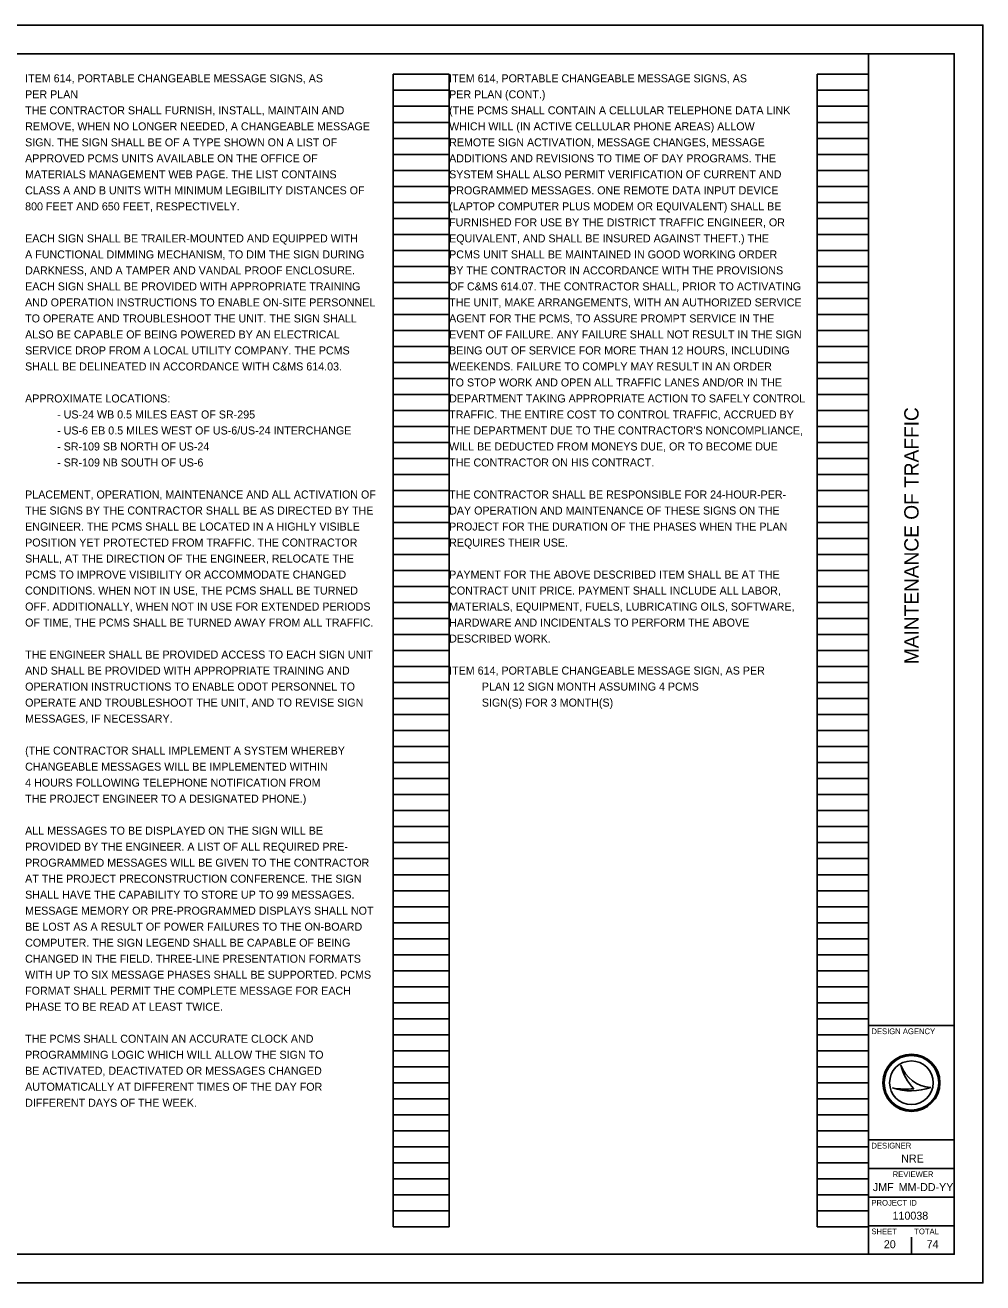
# Model space of a CAD drawing. Extents: x 0 to 34, y 0 to 22.
# Drawn here: x 17.24 to 34, y 0 to 22 of the extents above; entities that cross this region are included whole.
import ezdxf

# ---------------------------------------------------------------- set-up
doc = ezdxf.new("R2010")
doc.units = 0
for name, color, linetype in [('SH_Border', 7, 'Continuous'), ('SH_Cut_Line', 7, 'Continuous'), ('SH_Data', 7, 'Continuous'), ('SH_Text', 7, 'Continuous')]:
    doc.layers.add(name, color=color, linetype=linetype)

msp = doc.modelspace()

# ---------------------------------------------------------------- linework, layer by layer
at = {"layer": 'SH_Border'}
for p, q in [((32, 0.5), (32, 21.5)), ((32, 4.5), (33.5, 4.5)), ((32, 2.5), (33.5, 2.5)), ((32, 2), (33.5, 2)), ((32, 1.5), (33.5, 1.5)), ((32, 1), (33.5, 1))]:
    msp.add_line(p, q, dxfattribs=at)
msp.add_lwpolyline([(1.5, 21.5), (33.5, 21.5), (33.5, 0.5), (1.5, 0.5)], close=True, dxfattribs=at)
at = {"layer": 'SH_Cut_Line'}
msp.add_lwpolyline([(0, 0), (34, 0), (34, 22), (0, 22)], close=True, dxfattribs=at)
at = {"layer": 'SH_Data'}
for p, q in [((23.68, 0.98), (23.68, 21.14)), ((23.68, 21.14), (24.66, 21.14)), ((24.66, 0.98), (24.66, 21.14)), ((31.1, 0.98), (31.1, 21.14)), ((31.1, 21.14), (32, 21.14)), ((32, 0.98), (32, 21.14)), ((23.68, 20.86), (24.66, 20.86)), ((31.1, 20.86), (32, 20.86)), ((23.68, 20.58), (24.66, 20.58)), ((31.1, 20.58), (32, 20.58)), ((23.68, 20.3), (24.66, 20.3)), ((31.1, 20.3), (32, 20.3)), ((23.68, 20.02), (24.66, 20.02)), ((31.1, 20.02), (32, 20.02)), ((23.68, 19.74), (24.66, 19.74)), ((31.1, 19.74), (32, 19.74)), ((23.68, 19.46), (24.66, 19.46)), ((31.1, 19.46), (32, 19.46)), ((23.68, 19.18), (24.66, 19.18)), ((31.1, 19.18), (32, 19.18)), ((23.68, 18.9), (24.66, 18.9)), ((31.1, 18.9), (32, 18.9)), ((23.68, 18.62), (24.66, 18.62)), ((31.1, 18.62), (32, 18.62)), ((23.68, 18.34), (24.66, 18.34)), ((31.1, 18.34), (32, 18.34)), ((23.68, 18.06), (24.66, 18.06)), ((31.1, 18.06), (32, 18.06)), ((23.68, 17.78), (24.66, 17.78)), ((31.1, 17.78), (32, 17.78)), ((23.68, 17.5), (24.66, 17.5)), ((31.1, 17.5), (32, 17.5)), ((23.68, 17.22), (24.66, 17.22)), ((31.1, 17.22), (32, 17.22)), ((23.68, 16.94), (24.66, 16.94)), ((31.1, 16.94), (32, 16.94)), ((23.68, 16.66), (24.66, 16.66)), ((31.1, 16.66), (32, 16.66)), ((23.68, 16.38), (24.66, 16.38)), ((31.1, 16.38), (32, 16.38)), ((23.68, 16.1), (24.66, 16.1)), ((31.1, 16.1), (32, 16.1)), ((23.68, 15.82), (24.66, 15.82)), ((31.1, 15.82), (32, 15.82)), ((23.68, 15.54), (24.66, 15.54)), ((31.1, 15.54), (32, 15.54)), ((23.68, 15.26), (24.66, 15.26)), ((31.1, 15.26), (32, 15.26)), ((23.68, 14.98), (24.66, 14.98)), ((31.1, 14.98), (32, 14.98)), ((23.68, 14.7), (24.66, 14.7)), ((31.1, 14.7), (32, 14.7)), ((23.68, 14.42), (24.66, 14.42)), ((31.1, 14.42), (32, 14.42)), ((23.68, 14.14), (24.66, 14.14)), ((31.1, 14.14), (32, 14.14)), ((23.68, 13.86), (24.66, 13.86)), ((31.1, 13.86), (32, 13.86)), ((23.68, 13.58), (24.66, 13.58)), ((31.1, 13.58), (32, 13.58)), ((23.68, 13.3), (24.66, 13.3)), ((31.1, 13.3), (32, 13.3)), ((23.68, 13.02), (24.66, 13.02)), ((31.1, 13.02), (32, 13.02)), ((23.68, 12.74), (24.66, 12.74)), ((31.1, 12.74), (32, 12.74)), ((23.68, 12.46), (24.66, 12.46)), ((31.1, 12.46), (32, 12.46)), ((23.68, 12.18), (24.66, 12.18)), ((31.1, 12.18), (32, 12.18)), ((23.68, 11.9), (24.66, 11.9)), ((31.1, 11.9), (32, 11.9)), ((23.68, 11.62), (24.66, 11.62)), ((31.1, 11.62), (32, 11.62)), ((23.68, 11.34), (24.66, 11.34)), ((31.1, 11.34), (32, 11.34)), ((23.68, 11.06), (24.66, 11.06)), ((31.1, 11.06), (32, 11.06)), ((23.68, 10.78), (24.66, 10.78)), ((31.1, 10.78), (32, 10.78)), ((23.68, 10.5), (24.66, 10.5)), ((31.1, 10.5), (32, 10.5)), ((23.68, 10.22), (24.66, 10.22)), ((31.1, 10.22), (32, 10.22)), ((23.68, 9.94), (24.66, 9.94)), ((31.1, 9.94), (32, 9.94)), ((23.68, 9.66), (24.66, 9.66)), ((31.1, 9.66), (32, 9.66)), ((23.68, 9.38), (24.66, 9.38)), ((31.1, 9.38), (32, 9.38)), ((23.68, 9.1), (24.66, 9.1)), ((31.1, 9.1), (32, 9.1)), ((23.68, 8.82), (24.66, 8.82)), ((31.1, 8.82), (32, 8.82)), ((23.68, 8.54), (24.66, 8.54)), ((31.1, 8.54), (32, 8.54)), ((23.68, 8.26), (24.66, 8.26)), ((31.1, 8.26), (32, 8.26)), ((23.68, 7.98), (24.66, 7.98)), ((31.1, 7.98), (32, 7.98)), ((23.68, 7.7), (24.66, 7.7)), ((31.1, 7.7), (32, 7.7)), ((23.68, 7.42), (24.66, 7.42)), ((31.1, 7.42), (32, 7.42)), ((23.68, 7.14), (24.66, 7.14)), ((31.1, 7.14), (32, 7.14)), ((23.68, 6.86), (24.66, 6.86)), ((31.1, 6.86), (32, 6.86)), ((23.68, 6.58), (24.66, 6.58)), ((31.1, 6.58), (32, 6.58)), ((23.68, 6.3), (24.66, 6.3)), ((31.1, 6.3), (32, 6.3)), ((23.68, 6.02), (24.66, 6.02)), ((31.1, 6.02), (32, 6.02)), ((23.68, 5.74), (24.66, 5.74)), ((31.1, 5.74), (32, 5.74)), ((23.68, 5.46), (24.66, 5.46)), ((31.1, 5.46), (32, 5.46)), ((23.68, 5.18), (24.66, 5.18)), ((31.1, 5.18), (32, 5.18)), ((23.68, 4.9), (24.66, 4.9)), ((31.1, 4.9), (32, 4.9)), ((23.68, 4.62), (24.66, 4.62)), ((31.1, 4.62), (32, 4.62)), ((23.68, 4.34), (24.66, 4.34)), ((31.1, 4.34), (32, 4.34)), ((23.68, 4.06), (24.66, 4.06)), ((31.1, 4.06), (32, 4.06)), ((23.68, 3.78), (24.66, 3.78)), ((31.1, 3.78), (32, 3.78)), ((32.567, 3.81), (32.567, 3.81)), ((23.68, 3.5), (24.66, 3.5)), ((31.1, 3.5), (32, 3.5)), ((32.417, 3.41), (32.417, 3.41)), ((32.75, 3.5), (32.75, 3.5)), ((33.087, 3.419), (33.087, 3.419)), ((23.68, 3.22), (24.66, 3.22)), ((31.1, 3.22), (32, 3.22)), ((23.68, 2.94), (24.66, 2.94)), ((31.1, 2.94), (32, 2.94)), ((23.68, 2.66), (24.66, 2.66)), ((31.1, 2.66), (32, 2.66)), ((23.68, 2.38), (24.66, 2.38)), ((31.1, 2.38), (32, 2.38)), ((23.68, 2.1), (24.66, 2.1)), ((31.1, 2.1), (32, 2.1)), ((23.68, 1.82), (24.66, 1.82)), ((31.1, 1.82), (32, 1.82)), ((23.68, 1.54), (24.66, 1.54)), ((31.1, 1.54), (32, 1.54)), ((23.68, 1.26), (24.66, 1.26)), ((31.1, 1.26), (32, 1.26)), ((23.68, 0.98), (24.66, 0.98)), ((31.1, 0.98), (32, 0.98)), ((32.375, 0.675), (32.375, 0.675)), ((32.75, 0.5), (32.75, 0.8))]:
    msp.add_line(p, q, dxfattribs=at)
for radius in [0.5, 0.477, 0.477, 0.382]:
    msp.add_circle((32.75, 3.5), radius, dxfattribs=at)
for centre, radius, start, end in [((33.116, 3.998), 0.58, 198.9257, 198.9319), ((33.347, 3.97), 0.796, 191.6379, 191.6421), ((33.116, 3.998), 0.58, 198.9319, 267.1657), ((33.347, 3.97), 0.796, 191.6421, 226.0947), ((32.739, 4.37), 1.013, 251.4576, 290.0832), ((32.648, 4.654), 1.266, 259.4964, 259.4995), ((32.739, 4.37), 1.013, 251.4527, 251.4576), ((32.648, 4.654), 1.266, 259.4995, 276.6672)]:
    msp.add_arc(centre, radius, start, end, dxfattribs=at)

# ---------------------------------------------------------------- texts
msp.add_text('MAINTENANCE OF TRAFFIC', height=0.25, rotation=90, dxfattribs=at).set_placement((32.875, 10.822))
for s, height, p in [('DESIGN AGENCY', 0.1, (32.05, 4.35)), ('DESIGNER', 0.1, (32.05, 2.35)), ('NRE', 0.14, (32.571, 2.105)), ('REVIEWER', 0.1, (32.422, 1.85)), ('JMF', 0.14, (32.075, 1.605)), ('MM-DD-YY', 0.14, (32.527, 1.605)), ('PROJECT ID', 0.1, (32.05, 1.35)), ('110038', 0.14, (32.419, 1.105)), ('SHEET', 0.1, (32.05, 0.85)), ('TOTAL', 0.1, (32.8, 0.85)), ('20', 0.14, (32.267, 0.605)), ('74', 0.14, (33.016, 0.605))]:
    msp.add_text(s, height=height, dxfattribs=at).set_placement(p)
at = {"layer": 'SH_Text'}
for s, p in [('ITEM 614, PORTABLE CHANGEABLE MESSAGE SIGNS, AS', (17.24, 21)), ('ITEM 614, PORTABLE CHANGEABLE MESSAGE SIGNS, AS', (24.66, 21)), ('PER PLAN', (17.24, 20.72)), ('PER PLAN (CONT.)', (24.66, 20.72)), ('THE CONTRACTOR SHALL FURNISH, INSTALL, MAINTAIN AND', (17.24, 20.44)), ('(THE PCMS SHALL CONTAIN A CELLULAR TELEPHONE DATA LINK', (24.66, 20.44)), ('REMOVE, WHEN NO LONGER NEEDED, A CHANGEABLE MESSAGE', (17.24, 20.16)), ('WHICH WILL (IN ACTIVE CELLULAR PHONE AREAS) ALLOW', (24.66, 20.16)), ('SIGN. THE SIGN SHALL BE OF A TYPE SHOWN ON A LIST OF', (17.24, 19.88)), ('REMOTE SIGN ACTIVATION, MESSAGE CHANGES, MESSAGE', (24.66, 19.88)), ('APPROVED PCMS UNITS AVAILABLE ON THE OFFICE OF', (17.24, 19.6)), ('ADDITIONS AND REVISIONS TO TIME OF DAY PROGRAMS. THE', (24.66, 19.6)), ('MATERIALS MANAGEMENT WEB PAGE. THE LIST CONTAINS', (17.24, 19.32)), ('SYSTEM SHALL ALSO PERMIT VERIFICATION OF CURRENT AND', (24.66, 19.32)), ('CLASS A AND B UNITS WITH MINIMUM LEGIBILITY DISTANCES OF', (17.24, 19.04)), ('PROGRAMMED MESSAGES. ONE REMOTE DATA INPUT DEVICE', (24.66, 19.04)), ('800 FEET AND 650 FEET, RESPECTIVELY.', (17.24, 18.76)), ('(LAPTOP COMPUTER PLUS MODEM OR EQUIVALENT) SHALL BE', (24.66, 18.76)), ('FURNISHED FOR USE BY THE DISTRICT TRAFFIC ENGINEER, OR', (24.66, 18.48)), ('EACH SIGN SHALL BE TRAILER-MOUNTED AND EQUIPPED WITH', (17.24, 18.2)), ('EQUIVALENT, AND SHALL BE INSURED AGAINST THEFT.) THE', (24.66, 18.2)), ('A FUNCTIONAL DIMMING MECHANISM, TO DIM THE SIGN DURING', (17.24, 17.92)), ('PCMS UNIT SHALL BE MAINTAINED IN GOOD WORKING ORDER', (24.66, 17.92)), ('DARKNESS, AND A TAMPER AND VANDAL PROOF ENCLOSURE.', (17.24, 17.64)), ('BY THE CONTRACTOR IN ACCORDANCE WITH THE PROVISIONS', (24.66, 17.64)), ('EACH SIGN SHALL BE PROVIDED WITH APPROPRIATE TRAINING', (17.24, 17.36)), ('OF C&MS 614.07. THE CONTRACTOR SHALL, PRIOR TO ACTIVATING', (24.66, 17.36)), ('AND OPERATION INSTRUCTIONS TO ENABLE ON-SITE PERSONNEL', (17.24, 17.08)), ('THE UNIT, MAKE ARRANGEMENTS, WITH AN AUTHORIZED SERVICE', (24.66, 17.08)), ('TO OPERATE AND TROUBLESHOOT THE UNIT. THE SIGN SHALL', (17.24, 16.8)), ('AGENT FOR THE PCMS, TO ASSURE PROMPT SERVICE IN THE', (24.66, 16.8)), ('ALSO BE CAPABLE OF BEING POWERED BY AN ELECTRICAL', (17.24, 16.52)), ('EVENT OF FAILURE. ANY FAILURE SHALL NOT RESULT IN THE SIGN', (24.66, 16.52)), ('SERVICE DROP FROM A LOCAL UTILITY COMPANY. THE PCMS', (17.24, 16.24)), ('BEING OUT OF SERVICE FOR MORE THAN 12 HOURS, INCLUDING', (24.66, 16.24)), ('SHALL BE DELINEATED IN ACCORDANCE WITH C&MS 614.03.', (17.24, 15.96)), ('WEEKENDS. FAILURE TO COMPLY MAY RESULT IN AN ORDER', (24.66, 15.96)), ('TO STOP WORK AND OPEN ALL TRAFFIC LANES AND/OR IN THE', (24.66, 15.68)), ('APPROXIMATE LOCATIONS:', (17.24, 15.4)), ('DEPARTMENT TAKING APPROPRIATE ACTION TO SAFELY CONTROL', (24.66, 15.4)), ('- US-24 WB 0.5 MILES EAST OF SR-295', (17.8, 15.12)), ('TRAFFIC. THE ENTIRE COST TO CONTROL TRAFFIC, ACCRUED BY', (24.66, 15.12)), ('- US-6 EB 0.5 MILES WEST OF US-6/US-24 INTERCHANGE', (17.8, 14.84)), ("THE DEPARTMENT DUE TO THE CONTRACTOR'S NONCOMPLIANCE,", (24.66, 14.84)), ('- SR-109 SB NORTH OF US-24', (17.8, 14.56)), ('WILL BE DEDUCTED FROM MONEYS DUE, OR TO BECOME DUE', (24.66, 14.56)), ('- SR-109 NB SOUTH OF US-6', (17.8, 14.28)), ('THE CONTRACTOR ON HIS CONTRACT.', (24.66, 14.28)), ('PLACEMENT, OPERATION, MAINTENANCE AND ALL ACTIVATION OF', (17.24, 13.72)), ('THE CONTRACTOR SHALL BE RESPONSIBLE FOR 24-HOUR-PER-', (24.66, 13.72)), ('THE SIGNS BY THE CONTRACTOR SHALL BE AS DIRECTED BY THE', (17.24, 13.44)), ('DAY OPERATION AND MAINTENANCE OF THESE SIGNS ON THE', (24.66, 13.44)), ('ENGINEER. THE PCMS SHALL BE LOCATED IN A HIGHLY VISIBLE', (17.24, 13.16)), ('PROJECT FOR THE DURATION OF THE PHASES WHEN THE PLAN', (24.66, 13.16)), ('POSITION YET PROTECTED FROM TRAFFIC. THE CONTRACTOR', (17.24, 12.88)), ('REQUIRES THEIR USE.', (24.66, 12.88)), ('SHALL, AT THE DIRECTION OF THE ENGINEER, RELOCATE THE', (17.24, 12.6)), ('PCMS TO IMPROVE VISIBILITY OR ACCOMMODATE CHANGED', (17.24, 12.32)), ('PAYMENT FOR THE ABOVE DESCRIBED ITEM SHALL BE AT THE', (24.66, 12.32)), ('CONDITIONS. WHEN NOT IN USE, THE PCMS SHALL BE TURNED', (17.24, 12.04)), ('CONTRACT UNIT PRICE. PAYMENT SHALL INCLUDE ALL LABOR,', (24.66, 12.04)), ('OFF. ADDITIONALLY, WHEN NOT IN USE FOR EXTENDED PERIODS', (17.24, 11.76)), ('MATERIALS, EQUIPMENT, FUELS, LUBRICATING OILS, SOFTWARE,', (24.66, 11.76)), ('OF TIME, THE PCMS SHALL BE TURNED AWAY FROM ALL TRAFFIC.', (17.24, 11.48)), ('HARDWARE AND INCIDENTALS TO PERFORM THE ABOVE', (24.66, 11.48)), ('DESCRIBED WORK.', (24.66, 11.2)), ('THE ENGINEER SHALL BE PROVIDED ACCESS TO EACH SIGN UNIT', (17.24, 10.92)), ('AND SHALL BE PROVIDED WITH APPROPRIATE TRAINING AND', (17.24, 10.64)), ('ITEM 614, PORTABLE CHANGEABLE MESSAGE SIGN, AS PER', (24.66, 10.64)), ('OPERATION INSTRUCTIONS TO ENABLE ODOT PERSONNEL TO', (17.24, 10.36)), ('           PLAN 12 SIGN MONTH ASSUMING 4 PCMS', (24.66, 10.36)), ('OPERATE AND TROUBLESHOOT THE UNIT, AND TO REVISE SIGN', (17.24, 10.08)), ('           SIGN(S) FOR 3 MONTH(S)', (24.66, 10.08)), ('MESSAGES, IF NECESSARY.', (17.24, 9.8)), ('(THE CONTRACTOR SHALL IMPLEMENT A SYSTEM WHEREBY', (17.24, 9.24)), ('CHANGEABLE MESSAGES WILL BE IMPLEMENTED WITHIN', (17.24, 8.96)), ('4 HOURS FOLLOWING TELEPHONE NOTIFICATION FROM', (17.24, 8.68)), ('THE PROJECT ENGINEER TO A DESIGNATED PHONE.)', (17.24, 8.4)), ('ALL MESSAGES TO BE DISPLAYED ON THE SIGN WILL BE', (17.24, 7.84)), ('PROVIDED BY THE ENGINEER. A LIST OF ALL REQUIRED PRE-', (17.24, 7.56)), ('PROGRAMMED MESSAGES WILL BE GIVEN TO THE CONTRACTOR', (17.24, 7.28)), ('AT THE PROJECT PRECONSTRUCTION CONFERENCE. THE SIGN', (17.24, 7)), ('SHALL HAVE THE CAPABILITY TO STORE UP TO 99 MESSAGES.', (17.24, 6.72)), ('MESSAGE MEMORY OR PRE-PROGRAMMED DISPLAYS SHALL NOT', (17.24, 6.44)), ('BE LOST AS A RESULT OF POWER FAILURES TO THE ON-BOARD', (17.24, 6.16)), ('COMPUTER. THE SIGN LEGEND SHALL BE CAPABLE OF BEING', (17.24, 5.88)), ('CHANGED IN THE FIELD. THREE-LINE PRESENTATION FORMATS', (17.24, 5.6)), ('WITH UP TO SIX MESSAGE PHASES SHALL BE SUPPORTED. PCMS', (17.24, 5.32)), ('FORMAT SHALL PERMIT THE COMPLETE MESSAGE FOR EACH', (17.24, 5.04)), ('PHASE TO BE READ AT LEAST TWICE.', (17.24, 4.76)), ('THE PCMS SHALL CONTAIN AN ACCURATE CLOCK AND', (17.24, 4.2)), ('PROGRAMMING LOGIC WHICH WILL ALLOW THE SIGN TO', (17.24, 3.92)), ('BE ACTIVATED, DEACTIVATED OR MESSAGES CHANGED', (17.24, 3.64)), ('AUTOMATICALLY AT DIFFERENT TIMES OF THE DAY FOR', (17.24, 3.36)), ('DIFFERENT DAYS OF THE WEEK.', (17.24, 3.08))]:
    msp.add_text(s, height=0.14, dxfattribs=at).set_placement(p)

doc.saveas('drawing.dxf')
